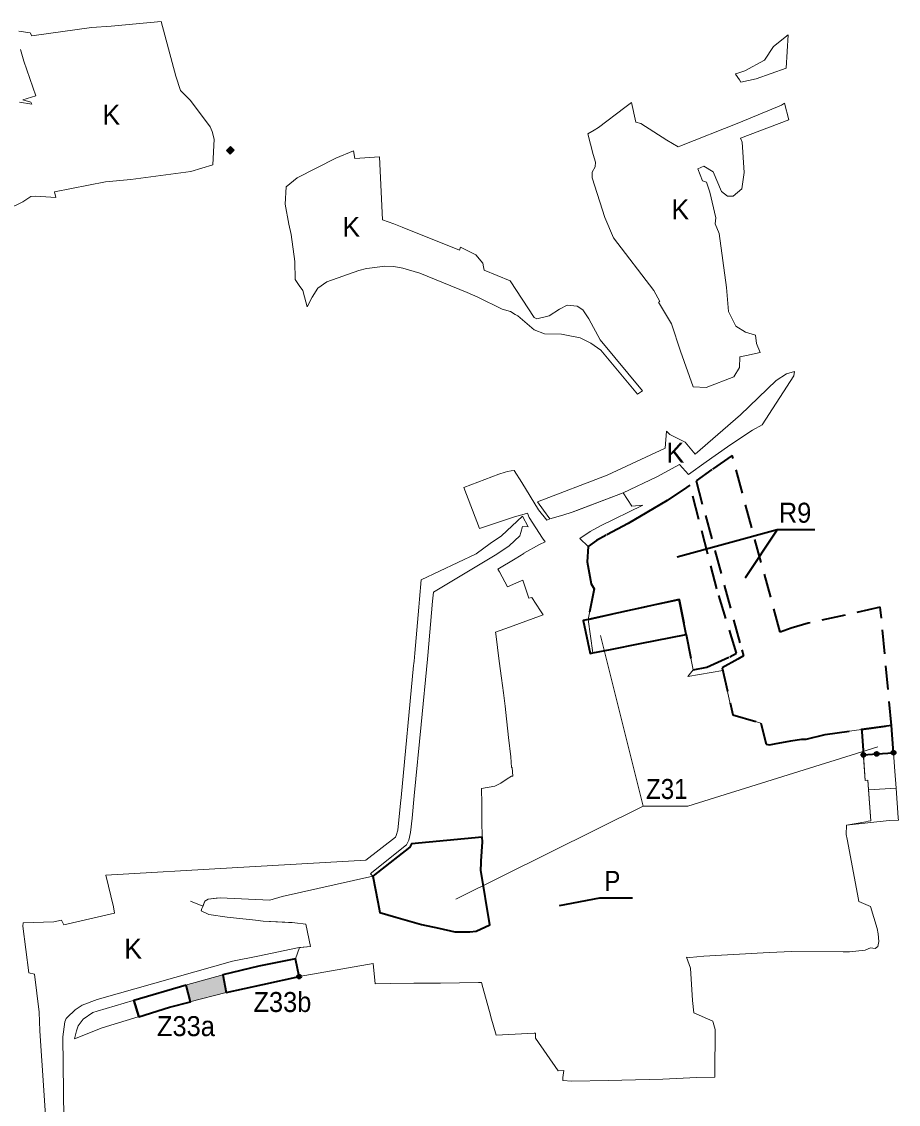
# Model space of a CAD drawing. Extents: x -650276 to -642489, y -1074425 to -1066658.
# Drawn here: x -644472 to -643419, y -1070307 to -1069008 of the extents above; entities that cross this region are included whole.
import ezdxf

# ---------------------------------------------------------------- set-up
doc = ezdxf.new("R2010")
doc.units = 0
doc.header["$LTSCALE"] = 9.6
doc.header["$PDMODE"] = 32
doc.header["$PDSIZE"] = 4.8
doc.linetypes.add('MEDIUM_DASHED', pattern=[4.5, 3, -1.5])
for name, color, linetype, lineweight in [('1', 7, 'Continuous', 13), ('43', 7, 'Continuous', 13), ('45', 7, 'Continuous', 40), ('46', 7, 'Continuous', 13), ('47', 7, 'Continuous', 13), ('60', 7, 'Continuous', 35), ('61', 7, 'MEDIUM_DASHED', 40), ('62', 7, 'Continuous', 35)]:
    doc.layers.add(name, color=color, linetype=linetype, lineweight=lineweight)

msp = doc.modelspace()

# ---------------------------------------------------------------- hatches: boundary and pattern name
at = {"layer": '1'}
for points in [[(-644221.63, -1069166.5), (-644216.9, -1069161.92), (-644221.09, -1069157.52), (-644225.85, -1069162.23)], [(-644226.23, -1070173.28), (-644230.4, -1070152.08), (-644275.05, -1070164.59), (-644269.84, -1070184.57)]]:
    msp.add_hatch(color=256, dxfattribs=at).paths.add_polyline_path(points)

# ---------------------------------------------------------------- linework, layer by layer
for points in [[(-644221.63, -1069166.5), (-644216.9, -1069161.92), (-644221.09, -1069157.52), (-644225.85, -1069162.23)], [(-644226.23, -1070173.28), (-644230.4, -1070152.08), (-644275.05, -1070164.59), (-644269.84, -1070184.57)], [(-644375.1, -1070215.79), (-644331.9, -1070202.4), (-644338.06, -1070182.64), (-644381.26, -1070195.59), (-644386.38, -1070197.2), (-644397.85, -1070205.13), (-644403.93, -1070213.28), (-644406.19, -1070219.32), (-644408.54, -1070228.87)]]:
    msp.add_lwpolyline(points, close=True, dxfattribs=at)
for points in [[(-643665.92, -1069785.96), (-643674.3, -1069743.53), (-643729.34, -1069754.3), (-643786.35, -1069765.46), (-643791.88, -1069725.25), (-643784.59, -1069688.47), (-643788.14, -1069682.71), (-643793.09, -1069656.07), (-643791.77, -1069637.88), (-643801.71, -1069628.02), (-643789.39, -1069619.67), (-643777.14, -1069613.01), (-643726.22, -1069588.03), (-643739.52, -1069589.29), (-643749.64, -1069573.35), (-643805.255, -1069594.489), (-643811.16, -1069596.45), (-643822.06, -1069600.07), (-643837.72, -1069604.62), (-643841.33, -1069606.06), (-643851.57, -1069593.88), (-643871.43, -1069560.98), (-643880.73, -1069546.36), (-643884.4, -1069547.02), (-643888.55, -1069547.78), (-643891.5, -1069548.31), (-643898.89, -1069551.06), (-643941.21, -1069566.85), (-643922.17, -1069616.26), (-643879.04, -1069601.78), (-643871.56, -1069599.63), (-643864.8, -1069597.7), (-643862.59, -1069602.92), (-643846.55, -1069627.51), (-643843.55, -1069632.12), (-643850.07, -1069635.49), (-643869.1, -1069645.78), (-643868.85, -1069646.21), (-643879.6, -1069652.65)], [(-643879.6, -1069652.65), (-643900.07, -1069664.92), (-643898.1, -1069668.26), (-643888.63, -1069686.33), (-643875.12, -1069680.07), (-643870.37, -1069678.12), (-643862.96, -1069699.89), (-643859.47, -1069699.1), (-643849.02, -1069715.11), (-643846.01, -1069719.71), (-643886.39, -1069734.49), (-643903.24, -1069740.66), (-643902.55, -1069742.76), (-643898.69, -1069775.37), (-643895.71, -1069795.81), (-643893.29, -1069813.42), (-643891.59, -1069829.51), (-643890.8, -1069837), (-643887.35, -1069866.84), (-643884.67, -1069890.08)], [(-643547.12, -1070123.91), (-643485.57, -1070124.21), (-643478.13, -1070124.25), (-643459.33, -1070122.38), (-643452.86, -1070119.74), (-643447.11, -1070120.36), (-643443.97, -1070117.9), (-643442.9, -1070112.05), (-643443.49, -1070102.74), (-643445.02, -1070096.17), (-643452.9, -1070069.97), (-643466.98, -1070063.76), (-643468.6, -1070054.97), (-643480.89, -1069988.97), (-643481.9, -1069983.68), (-643481.78, -1069972.39), (-643458.57, -1069968.17), (-643455.6, -1069967.63), (-643452.63, -1069967.09), (-643456.14, -1069918.26), (-643459.13, -1069918.47), (-643463.51, -1069857.44), (-643507.1, -1069863.33), (-643530.01, -1069869.17), (-643535.83, -1069869.23), (-643555.57, -1069872.38), (-643567.91, -1069874.7), (-643574.05, -1069875.85), (-643578.28, -1069874.97), (-643584.63, -1069849.66), (-643618, -1069840.01), (-643621.78, -1069824.57), (-643630.05, -1069786.46), (-643672, -1069793.92), (-643665.92, -1069785.96)], [(-643423.64, -1069907.59), (-643425.25, -1069885.25), (-643445.261, -1069886.692), (-643445.37, -1069886.7), (-643461.328, -1069887.84), (-643459.13, -1069918.47)], [(-643884.67, -1069890.08), (-643883.82, -1069902.98), (-643883.23, -1069902.88), (-643882.43, -1069913.54), (-643883.81, -1069913.64), (-643888.87, -1069916.781), (-643896.57, -1069921.83), (-643903.94, -1069925.59), (-643919.78, -1069928.09), (-643919.73, -1069930.79), (-643919.45, -1069944.39)], [(-643459.13, -1069918.47), (-643456.14, -1069918.26), (-643455.292, -1069930.059), (-643422.2, -1069927.68), (-643423.64, -1069907.59)], [(-643481.78, -1069972.39), (-643430.64, -1069966.78), (-643419.43, -1069966.34), (-643419.62, -1069963.66), (-643422.2, -1069927.68), (-643455.292, -1069930.059), (-643452.63, -1069967.09)], [(-643919.45, -1069944.39), (-643919.32, -1069950.49), (-643919.42, -1069957.44), (-643919.45, -1069959.53), (-643919.56, -1069967.29), (-643918.88, -1069986.82), (-643918.69, -1069992.23), (-643920.16, -1070015.69), (-643920.29, -1070017.73), (-643920.84, -1070026.46), (-643909.87, -1070091.95), (-643926.33, -1070099.5), (-643933.96, -1070100.18), (-643951.99, -1070100.35), (-643971.03, -1070095.79), (-643991.99, -1070091.37), (-644003.7, -1070088.06), (-644022.77, -1070082.66), (-644041.71, -1070077.29), (-644050.12, -1070033.64), (-644159.02, -1070057.84), (-644174.12, -1070062.16), (-644233.51, -1070059.54), (-644238.34, -1070059.92), (-644248.05, -1070061.33), (-644251.9, -1070063.55), (-644254.13, -1070069.08), (-644255.52, -1070072.5), (-644256.54, -1070075.02), (-644247.3, -1070079.69), (-644225.13, -1070082.95), (-644191.26, -1070086.47), (-644181.81, -1070087.51), (-644147.25, -1070089.35), (-644144.13, -1070089.47), (-644130.91, -1070091.1), (-644125, -1070117.83), (-644138.24, -1070119.29), (-644143.31, -1070132.95), (-644138.78, -1070154.07), (-644050.01, -1070138.19), (-644047.4, -1070162.68), (-644029.46, -1070162.44), (-644001.25, -1070162.03), (-643969.23, -1070161.95), (-643923.5, -1070161.3)], [(-643452.63, -1069967.09), (-643455.6, -1069967.63), (-643458.57, -1069968.17), (-643481.78, -1069972.39)], [(-643923.5, -1070161.3), (-643919.79, -1070161.15), (-643918.18, -1070167.04), (-643909.12, -1070200.22), (-643908.56, -1070202.27), (-643902.14, -1070224.35), (-643856.64, -1070221.95), (-643854.98, -1070221.87), (-643854.84, -1070228.19), (-643827.73, -1070267.3), (-643821.11, -1070266.91), (-643822.14, -1070275.37), (-643822.26, -1070278.85), (-643811.51, -1070279.84), (-643767.92, -1070278.79), (-643702.24, -1070277.22), (-643661.89, -1070275.34), (-643639.79, -1070274.68), (-643639.63, -1070253.09), (-643639.49, -1070235.43), (-643639.36, -1070217.78), (-643641.8, -1070209.42), (-643642.28, -1070207.75), (-643664.83, -1070197.66), (-643666.41, -1070182.7), (-643668.79, -1070144.14), (-643673.76, -1070130.59), (-643669.62, -1070131.03)], [(-643669.62, -1070131.03), (-643652.76, -1070129.53), (-643574.58, -1070125.37), (-643547.12, -1070123.91)]]:
    msp.add_lwpolyline(points, dxfattribs=at)
at = {"layer": '45'}
for p, q in [((-643461.327, -1069887.84), (-643445.37, -1069886.7)), ((-643445.37, -1069886.7), (-643425.253, -1069885.25)), ((-644138.78, -1070154.07), (-644143.31, -1070132.95)), ((-644182.31, -1070163.66), (-644138.78, -1070154.07))]:
    msp.add_line(p, q, dxfattribs=at)
for points in [[(-643791.88, -1069725.25), (-643797.75, -1069726.51), (-643789.3, -1069766.05), (-643786.35, -1069765.46), (-643764.94, -1069761.27), (-643729.34, -1069754.3), (-643674.3, -1069743.53), (-643682.61, -1069701.16)], [(-643791.88, -1069725.25), (-643797.75, -1069726.51), (-643789.3, -1069766.05), (-643786.35, -1069765.46), (-643764.94, -1069761.27), (-643729.34, -1069754.3), (-643674.3, -1069743.53), (-643682.61, -1069701.16)], [(-643920.84, -1070026.46), (-643920.29, -1070017.73), (-643920.16, -1070015.69), (-643918.69, -1069992.23), (-643918.88, -1069986.82), (-644004.06, -1069994.59), (-644005.92, -1069998.62), (-644044.7, -1070029.04), (-644050.12, -1070033.64), (-644044.18, -1070064.43), (-644041.71, -1070077.29), (-644022.77, -1070082.66), (-643991.99, -1070091.37), (-643971.03, -1070095.79), (-643951.99, -1070100.35), (-643933.96, -1070100.18), (-643926.33, -1070099.5), (-643909.87, -1070091.95)], [(-643920.84, -1070026.46), (-643920.29, -1070017.73), (-643920.16, -1070015.69), (-643918.69, -1069992.23), (-643918.88, -1069986.82), (-644004.06, -1069994.59), (-644005.92, -1069998.62), (-644044.7, -1070029.04), (-644050.12, -1070033.64), (-644044.18, -1070064.43), (-644041.71, -1070077.29), (-644022.77, -1070082.66), (-643991.99, -1070091.37), (-643971.03, -1070095.79), (-643951.99, -1070100.35), (-643933.96, -1070100.18), (-643926.33, -1070099.5), (-643909.87, -1070091.95)], [(-644274.246, -1070164.59), (-644337.256, -1070182.64), (-644331.096, -1070202.4), (-644294.206, -1070190.9), (-644269.036, -1070184.57)], [(-644274.246, -1070164.59), (-644337.256, -1070182.64), (-644331.096, -1070202.4), (-644294.206, -1070190.9), (-644269.036, -1070184.57)]]:
    msp.add_lwpolyline(points, close=True, dxfattribs=at)
for points in [[(-643425.253, -1069885.25), (-643427.6, -1069852.59), (-643463.51, -1069857.44)], [(-643463.51, -1069857.44), (-643463.31, -1069860.18), (-643461.327, -1069887.84)], [(-644143.31, -1070132.95), (-644143.31, -1070132.95), (-644143.31, -1070132.95), (-644187.11, -1070141.58), (-644230.4, -1070152.08), (-644226.23, -1070173.28), (-644182.31, -1070163.66)], [(-644143.31, -1070132.95), (-644143.31, -1070132.95), (-644143.31, -1070132.95), (-644187.11, -1070141.58), (-644230.4, -1070152.08), (-644226.23, -1070173.28), (-644182.31, -1070163.66)], [(-644182.31, -1070163.66), (-644138.78, -1070154.07), (-644143.31, -1070132.95)]]:
    msp.add_lwpolyline(points, dxfattribs=at)
for p in [(-643461.327, -1069887.84), (-643445.37, -1069886.7), (-643425.253, -1069885.25), (-644138.78, -1070154.07)]:
    msp.add_point(p, dxfattribs=at)
at = {"layer": '46'}
for points in [[(-643672.005, -1069949.473), (-643725.65, -1069949.473), (-643725.65, -1069949.473), (-643777.096, -1069744.435), (-643725.65, -1069949.473), (-643950.635, -1070061)], [(-643444.15, -1069878.232), (-643672.005, -1069949.473), (-643725.65, -1069949.473)]]:
    msp.add_lwpolyline(points, dxfattribs=at)
at = {"layer": '47'}
msp.add_line((-643785.6, -1069166.98), (-643782.92, -1069176.24), dxfattribs=at)
for points in [[(-644475.09, -1069018.99), (-644461.74, -1069020.83), (-644459.67, -1069024.41), (-644387.91, -1069014.64), (-644364.53, -1069012.83), (-644304.6, -1069007.55), (-644286.94, -1069073.19)], [(-644474.33, -1069104.22), (-644459.82, -1069106.73), (-644461.01, -1069104.36), (-644470.37, -1069101.55), (-644454.75, -1069096.51), (-644469.28, -1069054.8), (-644473.222, -1069040.994)], [(-644286.94, -1069073.19), (-644281.26, -1069090.19), (-644269.11, -1069102.31), (-644245.65, -1069133.66), (-644243.14, -1069139.47), (-644240.67, -1069148.58), (-644242.48, -1069179.49), (-644268.7, -1069187.42), (-644340.83, -1069197.13), (-644371.08, -1069199.84), (-644432.53, -1069212.02), (-644430.91, -1069218.82), (-644454.87, -1069217.05), (-644460.97, -1069217.61), (-644470.64, -1069224), (-644489.27, -1069233.04)], [(-643697.29, -1069149.7), (-643728.49, -1069129.95), (-643734.75, -1069128.3), (-643739.66, -1069104.58), (-643747.75, -1069110.71), (-643779.31, -1069134.63), (-643784.55, -1069137.77), (-643792.04, -1069142.27), (-643785.6, -1069166.98)], [(-643555.98, -1069105.57), (-643559.5, -1069107.98), (-643610.81, -1069129.04), (-643681.63, -1069157.04), (-643683.68, -1069157.86), (-643697.29, -1069149.7)], [(-643607.02, -1069152.34), (-643609.08, -1069147.64), (-643550.79, -1069125.24), (-643555.98, -1069105.57)], [(-643707.23, -1069344.52), (-643691.6, -1069370.3), (-643681.09, -1069403.24), (-643665.87, -1069446.1), (-643650.28, -1069446.91), (-643616.78, -1069433.81), (-643610.18, -1069422.91), (-643609.6, -1069409.99), (-643601.9, -1069408.43), (-643585.19, -1069404.76), (-643589.52, -1069393.88), (-643590.89, -1069383.9), (-643602.92, -1069380.53), (-643614.35, -1069373.28), (-643623.28, -1069355.47), (-643625.9, -1069326.77), (-643634.56, -1069262.02), (-643639.23, -1069250.38), (-643638.72, -1069242.94), (-643645.61, -1069212.25), (-643649.84, -1069200.4), (-643654.57, -1069198.77), (-643660.22, -1069184.11), (-643653.05, -1069180.98), (-643641.84, -1069187.68), (-643631.66, -1069211.67), (-643624.38, -1069217.27), (-643617.64, -1069217), (-643607.37, -1069208.43), (-643604.38, -1069188.48), (-643607.02, -1069152.34)], [(-644094.79, -1069171.27), (-644141.24, -1069195.17), (-644154.36, -1069206.06), (-644155.37, -1069226.72), (-644151.11, -1069250.7), (-644148.22, -1069263.22), (-644144.05, -1069295.67)], [(-644024.93, -1069250.23), (-644038.83, -1069245.65), (-644042.37, -1069169.77), (-644071.97, -1069171.72), (-644073.35, -1069162.84), (-644094.79, -1069171.27)], [(-643782.92, -1069176.24), (-643783.2, -1069181.85), (-643786.97, -1069188.11), (-643786.89, -1069195.02), (-643771.86, -1069242.77), (-643761.21, -1069267.12), (-643712.78, -1069330.24)], [(-643732.705, -1069454.79), (-643726.74, -1069450.72), (-643777.27, -1069389.71), (-643791.02, -1069364.54), (-643798.1, -1069353.51), (-643804.83, -1069348.99), (-643817.06, -1069348.14), (-643826.21, -1069352.92), (-643838.69, -1069360.79), (-643853.56, -1069364.44), (-643856.43, -1069362.68), (-643885.63, -1069318.72), (-643916.78, -1069305.89), (-643917.36, -1069302.04), (-643918.08, -1069297.33), (-643926.74, -1069287.37), (-643944.89, -1069278.32), (-643946.16, -1069281.84), (-644015.12, -1069254.24), (-644024.93, -1069250.23)], [(-644144.05, -1069295.67), (-644143.54, -1069317.05), (-644138.55, -1069324.23), (-644134.15, -1069330.45), (-644132.52, -1069338.02), (-644129.09, -1069349.83), (-644123.21, -1069338.41), (-644116.33, -1069327.36), (-644105.5, -1069320.03), (-644067.08, -1069306.15)], [(-644067.08, -1069306.15), (-644058.05, -1069304.02), (-644054.35, -1069303.55)], [(-644054.35, -1069303.55), (-644035.89, -1069301.02), (-644025.24, -1069301.38), (-644014.19, -1069303.36), (-643993.91, -1069309.57), (-643936.87, -1069332.93), (-643924.42, -1069338.29), (-643894.84, -1069352.76), (-643885.22, -1069355.58), (-643879.48, -1069359.13), (-643876.34, -1069360.61), (-643856.58, -1069377.59), (-643844.28, -1069382.26), (-643823.72, -1069382.61), (-643815.93, -1069384.23), (-643801.36, -1069387.23), (-643788.63, -1069393.7), (-643776.78, -1069401.87), (-643732.705, -1069454.79)], [(-643712.78, -1069330.24), (-643705.74, -1069343.54), (-643707.23, -1069344.52)], [(-643671.53, -1069551.1), (-643649.94, -1069535.93), (-643624.65, -1069517.85), (-643605.97, -1069505.47), (-643594.49, -1069498.17), (-643582.77, -1069491.76), (-643545.07, -1069432.89), (-643544.06, -1069427.6), (-643553.7, -1069430.44), (-643565.92, -1069438.4), (-643608.89, -1069479.72), (-643663.46, -1069526.87), (-643675.32, -1069512.62), (-643693.95, -1069503.38)], [(-643693.95, -1069503.38), (-643697.85, -1069499.21), (-643699.23, -1069519.48), (-643769.08, -1069551.96), (-643852.51, -1069584.08), (-643845.304, -1069594.087)], [(-643845.304, -1069594.087), (-643837.72, -1069604.62), (-643822.06, -1069600.07), (-643811.16, -1069596.45), (-643749.64, -1069573.35), (-643709.33, -1069554.14), (-643682.27, -1069539.41), (-643671.53, -1069551.1)], [(-644399.15, -1070188.55), (-644381.21, -1070181.71), (-644218.65, -1070135.75), (-644188.44, -1070129.43), (-644140.72, -1070119.57), (-644125, -1070117.83), (-644130.91, -1070091.1), (-644144.13, -1070089.47), (-644181.81, -1070087.51), (-644191.26, -1070086.47), (-644225.13, -1070082.95), (-644247.3, -1070079.69), (-644256.54, -1070075.02), (-644255.52, -1070072.5), (-644254.136, -1070069.079), (-644254.13, -1070069.08), (-644254.25, -1070069.37), (-644269.156, -1070063.55), (-644254.25, -1070069.37), (-644251.9, -1070063.55), (-644248.05, -1070061.33), (-644233.51, -1070059.54), (-644174.12, -1070062.16), (-644159.02, -1070057.84), (-644050.12, -1070033.64), (-644053.18, -1070030.57), (-644051.913, -1070029.549), (-644049.311, -1070027.453), (-644009.95, -1069995.74), (-644006.96, -1069990.34), (-644005.06, -1069981.28), (-644003.06, -1069964.06), (-644000.52, -1069937.19), (-643992.27, -1069851.31), (-643984.845, -1069772.863), (-643984.44, -1069768.58), (-643978.85, -1069703.4), (-643977.454, -1069692.683), (-643901.55, -1069646.92), (-643886.62, -1069636.87), (-643873.82, -1069625.05), (-643872.55, -1069620.75), (-643870.44, -1069613.56), (-643863.92, -1069613.9), (-643870.697, -1069601.241), (-643895.951, -1069625.069), (-643909.616, -1069634.267), (-643926.229, -1069646.367), (-643992.34, -1069677.76), (-643994.36, -1069701.05), (-643995.17, -1069710.42), (-643999.94, -1069765.62), (-644000.79, -1069775.42), (-644001.04, -1069778.063), (-644001.29, -1069780.7), (-644016.47, -1069938.99), (-644017.15, -1069945.93), (-644020.26, -1069978.38), (-644022.43, -1069984.87), (-644022.99, -1069986.58), (-644058.55, -1070014.4), (-644219.33, -1070023.53), (-644370.87, -1070032.13), (-644361.74, -1070070.32), (-644361.55, -1070070.345), (-644360.41, -1070077.91), (-644421.26, -1070091.99), (-644423.99, -1070086.17), (-644433.19, -1070088.37), (-644470.17, -1070089.43), (-644470.55, -1070093.61), (-644463.28, -1070149.42), (-644456.41, -1070151.18), (-644450.72, -1070196.97), (-644450.15, -1070219.06), (-644445.28, -1070290.84), (-644440.36, -1070362.62)], [(-644243.15, -1070849.89), (-644246.93, -1070850.52), (-644282.77, -1070863.19), (-644324.34, -1070877.71), (-644337.15, -1070878.64), (-644344.86, -1070875.09), (-644460.82, -1070727.21), (-644465.31, -1070713.25), (-644468.1, -1070704.23), (-644467.84, -1070682.37), (-644466.998, -1070678.065), (-644463.28, -1070659.06), (-644458.85, -1070579.04), (-644455.2, -1070554.88), (-644418.69, -1070433.36), (-644418.23, -1070415.62), (-644421.45, -1070325.29), (-644422.5, -1070226.42), (-644420.14, -1070208.56), (-644418.61, -1070204.51), (-644417.36, -1070203.24), (-644407.55, -1070194.16), (-644399.15, -1070188.55)]]:
    msp.add_lwpolyline(points, dxfattribs=at)
msp.add_lwpolyline([(-643589.94, -1069076.36), (-643554.17, -1069063.59), (-643551.72, -1069023.19), (-643569.44, -1069037.24), (-643580.21, -1069053.96), (-643603.72, -1069066.5), (-643614.36, -1069070.29), (-643614.82, -1069070.45), (-643610.31, -1069077.52), (-643608.65, -1069080.11)], close=True, dxfattribs=at)
at = {"layer": '60'}
msp.add_lwpolyline([(-643738.691, -1070059.84), (-643778.124, -1070059.84), (-643826.476, -1070069.235)], dxfattribs=at)
at = {"layer": '61'}
for points in [[(-643561.41, -1069740.406), (-643618.737, -1069528.647), (-643643.16, -1069545.42), (-643662.335, -1069558.944), (-643607.44, -1069761.72), (-643605.24, -1069768.92), (-643612.22, -1069772.9), (-643630.77, -1069783.44), (-643618, -1069840.01), (-643584.63, -1069849.66), (-643578.28, -1069874.97), (-643574.05, -1069875.85), (-643567.91, -1069874.7), (-643548.67, -1069871.08), (-643535.83, -1069869.23), (-643530.01, -1069869.17), (-643507.1, -1069863.33), (-643463.51, -1069857.44), (-643427.6, -1069852.59), (-643440.77, -1069713.85), (-643441.08, -1069710.59), (-643527.49, -1069729.78), (-643547.9, -1069735.62)], [(-643743.81, -1069610.19), (-643770.29, -1069624.14), (-643781.95, -1069630.63), (-643791.77, -1069637.88), (-643793.09, -1069656.07), (-643788.14, -1069682.71), (-643784.59, -1069688.47), (-643791.88, -1069725.25), (-643682.61, -1069701.16), (-643674.3, -1069743.53), (-643665.92, -1069785.96), (-643649.25, -1069782.43), (-643621.71, -1069770.11), (-643613.9, -1069765.6), (-643637.36, -1069688.73), (-643669.73, -1069564.16), (-643673.82, -1069567.04), (-643697, -1069582.64), (-643721.43, -1069596.72)]]:
    msp.add_lwpolyline(points, close=True, dxfattribs=at)
at = {"layer": '62'}
msp.add_lwpolyline([(-643519.721, -1069617.808), (-643564.914, -1069617.808), (-643602.876, -1069674.79), (-643564.914, -1069617.808), (-643685.127, -1069650.369)], dxfattribs=at)
at = {"layer": '62', "lineweight": 13}
msp.add_lwpolyline([(-643519.721, -1069617.808), (-643564.914, -1069617.808), (-643602.876, -1069674.79), (-643564.914, -1069617.808), (-643685.127, -1069650.369)], dxfattribs=at)

# ---------------------------------------------------------------- texts
at = {"layer": '43'}
for p in [(-644374.971, -1069131.317), (-643691.928, -1069244.995), (-644086.887, -1069265.894), (-643697.851, -1069536.996), (-644348.839, -1070132.426)]:
    msp.add_text('K', height=24, dxfattribs=at).set_placement(p)
at = {"layer": '46'}
for s, width, p in [('Z31', 0.9, (-643722.294, -1069940.847)), ('Z33b', 0.95, (-644193.607, -1070196.61)), ('Z33b', 0.95, (-644193.607, -1070196.61)), ('Z33a', 0.95, (-644309.424, -1070225.565)), ('Z33a', 0.95, (-644309.424, -1070225.565))]:
    msp.add_text(s, height=24, dxfattribs=dict(at, width=width)).set_placement(p)
at = {"layer": '60', "width": 0.9}
msp.add_text('P', height=24, dxfattribs=at).set_placement((-643772.431, -1070051.2))
msp.add_text('P', height=24, dxfattribs=at).set_placement((-643772.431, -1070051.2))
at = {"layer": '62', "width": 0.95}
msp.add_text('R9', height=24, dxfattribs=at).set_placement((-643562.88, -1069609.148))
msp.add_text('R9', height=24, dxfattribs=at).set_placement((-643562.88, -1069609.148))

doc.saveas('drawing.dxf')
